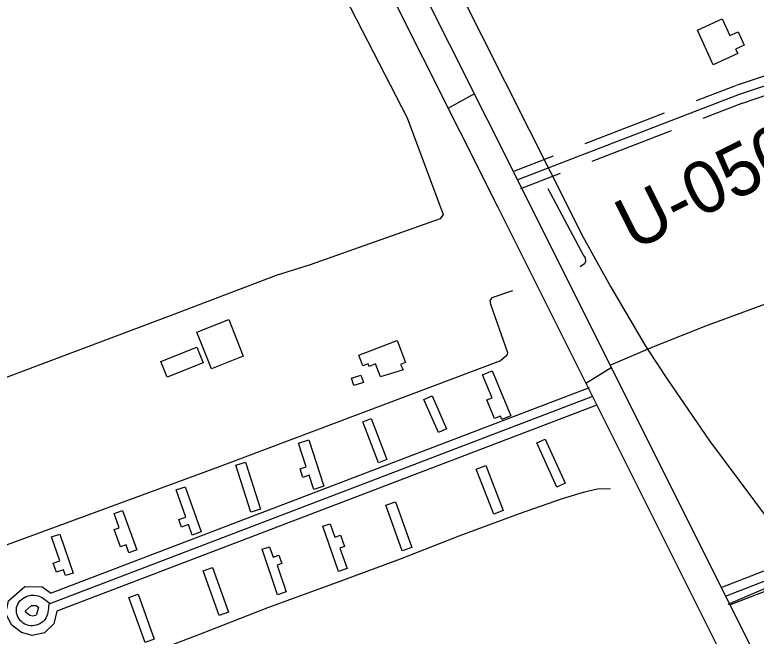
# Model space of a CAD drawing. Extents: x 3684037 to 3722149, y 433263 to 459021.
# Drawn here: x 3706676 to 3707859, y 439830 to 440822 of the extents above; entities that cross this region are included whole.
import ezdxf

# ---------------------------------------------------------------- set-up
doc = ezdxf.new("R2010")
doc.units = 0
for name, color, linetype in [('V-BLDG-OTLN', 7, 'Continuous'), ('V-DTCH-CNTR', 7, 'Continuous'), ('V-RAIL-TRAK', 7, 'Continuous'), ('V-RIVR-EDGE', 7, 'Continuous'), ('V-RIVR-RANG-IDEN', 7, 'Continuous'), ('V-ROAD-CNTR', 7, 'Continuous'), ('V-SITE-VEGE', 7, 'Continuous'), ('V-TOPO-SHOR', 7, 'Continuous')]:
    doc.layers.add(name, color=color, linetype=linetype)

msp = doc.modelspace()

# ---------------------------------------------------------------- linework, layer by layer
at = {"layer": 'V-BLDG-OTLN'}
for points in [[(3707790.5, 440742.6), (3707765.4, 440797.9), (3707804.6, 440815.8), (3707816.7, 440789.2), (3707830.2, 440795.4), (3707840, 440774), (3707826.2, 440767.8), (3707829.6, 440760.4)], [(3706989.7, 440257.1), (3706966.4, 440315.4), (3707017, 440335.6), (3707040.3, 440277.3)], [(3707259.2, 440244.1), (3707251.3, 440264.7), (3707241.2, 440260.9), (3707239.7, 440264.9), (3707231.4, 440261.7), (3707224.9, 440278.6), (3707285.8, 440302.1), (3707299.4, 440267), (3707291.4, 440263.9), (3707295.7, 440255.4)], [(3706908.9, 440268.7), (3706966.1, 440291.4), (3706976.1, 440266.5), (3706918.8, 440243.8)], [(3707467.2, 440181.7), (3707453, 440175.9), (3707450.8, 440181.5), (3707441.5, 440177.6), (3707429.3, 440207.3), (3707437.4, 440210.6), (3707422.3, 440247.5), (3707437.6, 440253.8)], [(3707212.9, 440241.9), (3707228.2, 440247), (3707232.1, 440235.2), (3707216.8, 440230.2)], [(3707351.8, 440155.4), (3707328.6, 440207.9), (3707341.7, 440213.7), (3707364.9, 440161.2)], [(3707256, 440107), (3707231, 440172.4), (3707244.5, 440177.6), (3707269.5, 440112.1)], [(3707168.9, 440069.4), (3707152.9, 440064.3), (3707145.7, 440086.9), (3707135.4, 440083.6), (3707131, 440097.1), (3707140.8, 440100.2), (3707128.7, 440138.1), (3707145.2, 440143.4)], [(3707540.7, 440068), (3707508.8, 440138.7), (3707522.1, 440144.7), (3707554, 440074.1)], [(3707052.5, 440027.9), (3707028.5, 440103.1), (3707043.9, 440108), (3707067.9, 440032.8)], [(3707440.3, 440024.8), (3707412.3, 440096.9), (3707427.3, 440102.7), (3707455.3, 440030.6)], [(3706973, 439996.5), (3706958.7, 439991.4), (3706952.8, 440008.1), (3706941.7, 440004.2), (3706937.4, 440016.2), (3706948.7, 440020.2), (3706933.3, 440063.6), (3706947.3, 440068.6)], [(3707293.7, 439966.1), (3707267.7, 440039), (3707283.4, 440044.6), (3707309.4, 439971.7)], [(3706870.2, 439967.6), (3706857.7, 439963.1), (3706853.2, 439975.6), (3706844.4, 439972.4), (3706834.3, 440000.3), (3706842.3, 440003.2), (3706834.1, 440025.9), (3706847.5, 440030.7)], [(3707192.4, 439933.3), (3707167.1, 440005.5), (3707178.9, 440009.6), (3707186.5, 439988), (3707195.4, 439991.2), (3707201.8, 439973), (3707194.6, 439970.5), (3707206, 439938.1)], [(3706747.4, 439992.9), (3706768.7, 439930.7), (3706756.7, 439926.6), (3706753.4, 439936.1), (3706742, 439932.1), (3706737.1, 439946.5), (3706747.4, 439950.1), (3706734.3, 439988.4)], [(3707094.8, 439895.9), (3707070.2, 439968.8), (3707082.3, 439972.9), (3707087.9, 439956.3), (3707097.3, 439959.5), (3707101.9, 439945.9), (3707094.6, 439943.4), (3707109, 439900.7)], [(3706991.3, 439939.5), (3707016.7, 439868.1), (3707001.8, 439862.8), (3706976.4, 439934.2)], [(3706872.6, 439897.2), (3706898.3, 439825), (3706883.5, 439819.7), (3706857.7, 439891.9)]]:
    msp.add_lwpolyline(points, close=True, dxfattribs=at)
at = {"layer": 'V-DTCH-CNTR'}
msp.add_lwpolyline([(3707814.5, 439880.9), (3707862.7, 439901.8), (3707944, 439936.4), (3707968.1, 439946.6), (3708014.3, 439966), (3708133.5, 440010.7)], dxfattribs=at)
at = {"layer": 'V-RAIL-TRAK'}
msp.add_lwpolyline([(3706745.4, 442138.7), (3706864.5, 441901.8), (3706943.3, 441742.1), (3707036.6, 441555.8), (3707107.8, 441414.2), (3707216.7, 441197.4), (3707250, 441130.8), (3707344.6, 440941.6), (3707496.5, 440638.8), (3707529.5, 440573.1), (3707582.9, 440467), (3707626.4, 440388.6), (3707681.8, 440294.3), (3707685.6, 440288.5), (3707717.4, 440240.1), (3707784.4, 440141.8), (3707880, 440014), (3707886.8, 440006)], dxfattribs=at)
at = {"layer": 'V-RIVR-EDGE'}
msp.add_spline([(3705459.3, 448025.4), (3705478.2, 447991), (3705490.6, 447962.7), (3705497.9, 447946.9), (3705515.2, 447915.3), (3705550.2, 447853.8), (3705577.2, 447806.4), (3705592.1, 447777.2), (3705613, 447735.5), (3705627.1, 447702.7), (3705648.4, 447660.6), (3705670.9, 447613.3), (3705688.6, 447575.6), (3705703.1, 447542.8), (3705728.1, 447487.8), (3705750.2, 447433.1), (3705764.2, 447399.5), (3705787.6, 447350.5), (3705800.4, 447321.8), (3705823.8, 447277.7), (3705853.1, 447212.9), (3705867.2, 447179.7), (3705884.5, 447148.5), (3705906.2, 447095.5), (3705936, 447039.6), (3705952.5, 446996.3), (3705954.5, 446986.6), (3705964.5, 446959.1), (3705978.2, 446928.3), (3706001.9, 446883.8), (3706017.2, 446850.2), (3706031.3, 446824.3), (3706060.3, 446774.8), (3706084.9, 446736.8), (3706095.8, 446723.4), (3706096.2, 446720.2), (3706091.3, 446714.5), (3706089.7, 446713.3), (3706090.5, 446708.9), (3706096.1, 446705.6), (3706103, 446703.6), (3706108.6, 446696.7), (3706116.3, 446683.3), (3706130, 446657), (3706163.4, 446591.8), (3706169.4, 446575.6), (3706187.1, 446537.6), (3706212.8, 446473.6), (3706230.1, 446432.3), (3706247.4, 446398.3), (3706265.1, 446371.2), (3706278.8, 446345.3), (3706293.7, 446309.7), (3706314.6, 446262.3), (3706333.5, 446225.8), (3706356, 446180.1), (3706380.2, 446133.5), (3706396.3, 446102.4), (3706412.8, 446074.8), (3706429.7, 446038.8), (3706447, 445997.9), (3706455.4, 445962.3), (3706478.2, 445886.2), (3706492.7, 445852.2), (3706510.4, 445809.7), (3706528.1, 445771.7), (3706558.3, 445705.3), (3706582.8, 445657.1), (3706597.7, 445624.3), (3706628.3, 445558.3), (3706659.6, 445483), (3706677.7, 445432.8), (3706697, 445381), (3706750.1, 445262.4), (3706782.6, 445193.2), (3706806.8, 445141.8), (3706827.7, 445093.6), (3706851, 445029.3), (3706864.2, 444984.3), (3706871.8, 444949.5), (3706889.5, 444896.9), (3706899.9, 444865.8), (3706912.4, 444832.2), (3706928.8, 444798.2), (3706942.5, 444773.5), (3706966.3, 444725.3), (3706990.4, 444679.5), (3707017, 444624.5), (3707033.9, 444586), (3707080.5, 444482), (3707095.4, 444444.7), (3707112.3, 444405.1), (3707123.1, 444381.2), (3707171.4, 444273.5), (3707203.2, 444200.6), (3707218, 444163.8), (3707250.2, 444096.2), (3707257.4, 444074.3), (3707269.9, 444041.6), (3707288.4, 443990.6), (3707304, 443950.1), (3707343, 443838), (3707365.9, 443772), (3707378.7, 443728.7), (3707379.9, 443714.1), (3707381.1, 443702.8), (3707387.5, 443682.2), (3707398.3, 443657.1), (3707418.1, 443619), (3707439, 443578.5), (3707454.3, 443542.1), (3707473.1, 443492.7), (3707483.2, 443464.4), (3707531.1, 443368), (3707542.7, 443345), (3707550.8, 443323.9), (3707556.8, 443302.5), (3707556.8, 443297.6), (3707558.8, 443289.1), (3707568.4, 443273.3), (3707583.7, 443244.6), (3707593.8, 443221.9), (3707598.2, 443213.4), (3707609.5, 443204.9), (3707611.9, 443195.2), (3707611.9, 443180.6), (3707615.5, 443168.1), (3707621.9, 443150.3), (3707634.4, 443126.8), (3707648.1, 443102.1), (3707655.3, 443081.8), (3707660.5, 443073.3), (3707674.2, 443051.5), (3707678.6, 443034.1), (3707682.6, 443015.5), (3707689.5, 442998.5), (3707701.9, 442964.5), (3707714, 442928.4), (3707721.2, 442903.3), (3707726.4, 442888.8), (3707738.1, 442871.8), (3707743.7, 442857.2), (3707744.5, 442845.1), (3707747.3, 442826.1), (3707753.7, 442815.5), (3707763, 442801.3), (3707770.2, 442783.9), (3707772.6, 442762.1), (3707776.2, 442738.2), (3707779.8, 442720), (3707786.6, 442702.6), (3707805.5, 442663.3), (3707822.8, 442627.3), (3707832, 442599.4), (3707839.2, 442573.9), (3707845.7, 442561.3), (3707852.5, 442552.4), (3707860.2, 442541.9), (3707869.5, 442530.6), (3707886.4, 442507.9), (3707898.9, 442479.9), (3707916.1, 442434.6), (3707928.6, 442395.8), (3707943.4, 442356.5), (3707965.6, 442316.4), (3707989.7, 442269), (3708009.8, 442227.7), (3708024.7, 442192.5), (3708061.3, 442114.4), (3708074.2, 442088.5), (3708094.3, 442045.6), (3708116, 441996.6), (3708126.1, 441968.3), (3708137.7, 441927.8), (3708147.3, 441899.5), (3708157.8, 441868.3), (3708179.1, 441812.4), (3708204, 441746.9), (3708227.7, 441693.8), (3708249.8, 441646.1), (3708265.1, 441615.3), (3708271.5, 441595.9), (3708278.4, 441582.1), (3708308.1, 441508.4), (3708330.6, 441457.8), (3708349.9, 441405.2), (3708369.6, 441340.1), (3708384, 441295.6), (3708395.3, 441268.4), (3708411.8, 441234.8), (3708423.4, 441209.3), (3708441.1, 441169.7), (3708458.4, 441135.2), (3708469.3, 441110.5), (3708475.3, 441089.1), (3708486.9, 441061.6), (3708507.1, 441017.4), (3708523.5, 440978.6), (3708539.2, 440935.7), (3708564.1, 440883.1), (3708587.1, 440841.3), (3708595.1, 440826.8), (3708600.4, 440809.4), (3708606.7, 440778.2), (3708615.6, 440755.1), (3708636.9, 440692), (3708652.9, 440644.3), (3708673.4, 440592), (3708688.7, 440554.4), (3708706, 440506.6), (3708725.7, 440462.9), (3708743.4, 440422.4), (3708759.4, 440387.6), (3708800.1, 440293.3), (3708821, 440246.3), (3708835, 440211.5), (3708849.1, 440180.4), (3708876.1, 440124.9), (3708892.2, 440093.7), (3708912.3, 440054.9), (3708922.3, 440031), (3708932, 439999.8), (3708939.2, 439978.8), (3708948, 439954.1), (3708952.4, 439931.8), (3708956, 439911.6), (3708960, 439899.5), (3708969.6, 439870.3), (3708986.9, 439829.8), (3708999.4, 439794.2), (3709014.7, 439755.4), (3709034.7, 439705.2), (3709046.8, 439671.6), (3709063.3, 439633.1), (3709075.8, 439614.5), (3709093.1, 439592.6), (3709106, 439574.4), (3709121.7, 439548.9), (3709151.5, 439484.1), (3709171.6, 439447.3), (3709197.4, 439407.6), (3709211.1, 439376.8), (3709222.3, 439350.1), (3709240.4, 439308.8), (3709252.9, 439281.7), (3709266.1, 439254.9), (3709271, 439245.6), (3709296.3, 439199.9), (3709313.2, 439159), (3709331.3, 439114.9), (3709341.3, 439082.5), (3709360.3, 439046.5), (3709378.8, 439008.8), (3709407.7, 438944.4), (3709416.4, 438923.6)], degree=3, dxfattribs=at)
at = {"layer": 'V-ROAD-CNTR'}
for points in [[(3706492.4, 442521.2), (3706946.8, 441617.1), (3707489, 440536.5), (3707877, 439759.9), (3708257.7, 438990.5)], [(3706450.1, 442499.9), (3706904.6, 441595.9), (3707446.7, 440515.3), (3707834.7, 439738.8), (3708246.6, 438913.6)], [(3707477.7, 440558.9), (3707832.2, 440695.7), (3708200.2, 440818.4)], [(3707827.5, 440710), (3707893.2, 440731.9)], [(3707763.5, 440685.3), (3707826.8, 440709.7)], [(3707837, 440681.5), (3707902.7, 440703.4)], [(3707367.4, 440673.3), (3707408.7, 440696.4)], [(3707774.3, 440657.3), (3707837.6, 440681.7)], [(3707586.3, 440616.8), (3707712.9, 440665.7)], [(3707597.1, 440588.9), (3707723.7, 440637.7)], [(3707472.3, 440572.9), (3707535.6, 440597.3)], [(3707483.1, 440544.9), (3707546.4, 440569.3)], [(3707626.9, 440263.6), (3707685.6, 440288.5), (3707698.1, 440293.8), (3707778.7, 440325.6), (3708256.3, 440501.9)], [(3707587.3, 440233.9), (3707627.6, 440258.9)], [(3707592.6, 440226.6), (3706733.8, 439898.6)], [(3707597.9, 440212.6), (3706729.7, 439881), (3706729.7, 439881)], [(3707603.3, 440198.6), (3706742.5, 439869.8)], [(3707803.3, 439907.5), (3708499.8, 440178.8)], [(3707810, 439893.9), (3708507.8, 440165.1)], [(3707816.9, 439880.2), (3708512.4, 440149.3)], [(3706742.5, 439869.8), (3706737.7, 439849.4), (3706723.2, 439835.3), (3706703.5, 439831.2), (3706686.5, 439835.6), (3706670.7, 439847.5), (3706661.3, 439865.7), (3706665.4, 439886.3), (3706691.4, 439909.5), (3706719.1, 439908.5), (3706733.8, 439898.6)], [(3706713.2, 439876.3), (3706710.5, 439864.8), (3706708.5, 439862.9), (3706704.2, 439862), (3706699.8, 439863.2), (3706694.2, 439867.3), (3706692.8, 439870.1), (3706692.9, 439870.6), (3706702.4, 439879.1), (3706709.4, 439878.9), (3706713.2, 439876.3)]]:
    msp.add_lwpolyline(points, dxfattribs=at)
msp.add_spline([(3706729.7, 439881), (3706724.1, 439857.1), (3706703.9, 439846.6), (3706682.4, 439857.4), (3706679.2, 439878.4), (3706696.9, 439894.3), (3706714.3, 439893.7), (3706731.8, 439881.8)], degree=3, dxfattribs=at)
at = {"layer": 'V-SITE-VEGE'}
msp.add_lwpolyline([(3707130.2, 440992.2), (3707301.9, 440657.6), (3707359.4, 440503.7), (3707354.6, 440496.6), (3707147.1, 440423.1), (3707092.7, 440406.2), (3706923.4, 440341.6), (3706626.4, 440229.8)], dxfattribs=at)
at = {"layer": 'V-TOPO-SHOR'}
for points in [[(3707526.6, 440545.2), (3707583.3, 440438), (3707586.1, 440434.5), (3707586.7, 440428.6), (3707584.9, 440424.5), (3707578, 440419.7)], [(3707470.1, 440381.5), (3707436.8, 440370.1), (3707433.8, 440366.1), (3707434.9, 440360.2), (3707462, 440283.2)], [(3707462, 440283.2), (3707461.4, 440279.7), (3707459, 440276.8), (3707450.8, 440269.9), (3707001.7, 440100.4), (3706653.2, 439972.3), (3706565.2, 439936.5)], [(3707626.5, 440065.5), (3707605.5, 440064.9), (3707582.9, 440059.5), (3707549.2, 440049.3), (3707480.8, 440025.5), (3707384.6, 439989.5), (3707290.7, 439953), (3707188.7, 439915.1), (3707080.4, 439875.7), (3706966.4, 439831), (3706813.3, 439773.2), (3706731, 439743.5), (3706702.2, 439731.4), (3706688.2, 439726.5), (3706681.8, 439724.3)]]:
    msp.add_lwpolyline(points, dxfattribs=at)

# ---------------------------------------------------------------- texts
at = {"layer": 'V-RIVR-RANG-IDEN'}
msp.add_text('U-050', height=83, rotation=26.5493, dxfattribs=at).set_placement((3707662.6, 440444.4))

doc.saveas('drawing.dxf')
